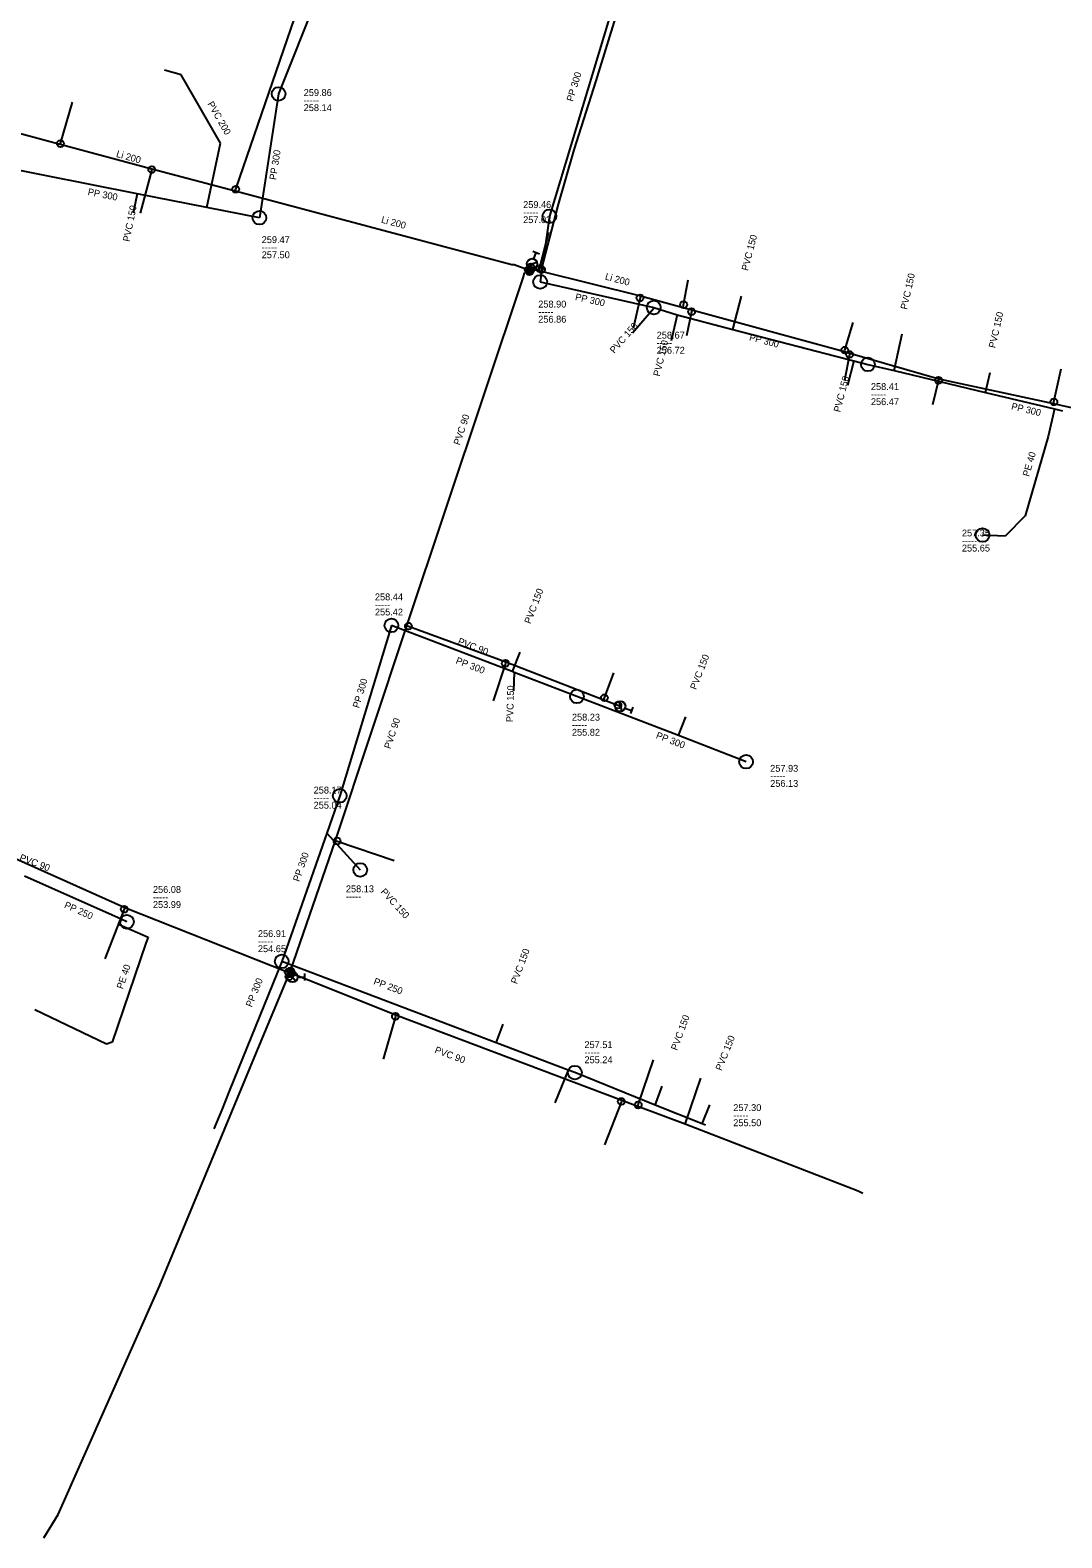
# Model space of a CAD drawing. Extents: x -771681 to -770485, y -1050143 to -1049574.
# Drawn here: x -770902.2 to -770751.8, y -1050118.2 to -1049898.6 of the extents above; entities that cross this region are included whole.
import ezdxf

# ---------------------------------------------------------------- set-up
doc = ezdxf.new("R2010")
doc.units = 0
doc.layers.add('Level 0', color=7, linetype='Continuous')

msp = doc.modelspace()

# ---------------------------------------------------------------- linework, layer by layer
at = {"layer": 'Level 0'}
for p, q in [((-770872.22, -1049921.74), (-770853.82, -1049868.4)), ((-770858.09, -1049887.99), (-770865.96, -1049907.86)), ((-770817.79, -1049896.87), (-770826.51, -1049925.68)), ((-770819.69, -1049905.97), (-770816.69, -1049896.18)), ((-770880.16, -1049905.07), (-770882.61, -1049904.41)), ((-770874.42, -1049915.05), (-770880.16, -1049905.07)), ((-770822.88, -1049916), (-770819.69, -1049905.97)), ((-770865.96, -1049907.86), (-770868.76, -1049925.9)), ((-770897.76, -1049915.1), (-770896.01, -1049909.08)), ((-770905.19, -1049913.2), (-770899.25, -1049914.79)), ((-770899.25, -1049914.79), (-770897.79, -1049915.2)), ((-770897.79, -1049915.2), (-770897.76, -1049915.1)), ((-770876.41, -1049924.39), (-770874.42, -1049915.05)), ((-770897.79, -1049915.2), (-770884.42, -1049918.76)), ((-770825.21, -1049924.11), (-770822.88, -1049916)), ((-770886.57, -1049922.39), (-770910.53, -1049917.67)), ((-770884.45, -1049918.87), (-770886.12, -1049925.24)), ((-770884.42, -1049918.76), (-770884.45, -1049918.87)), ((-770884.42, -1049918.76), (-770872.3, -1049921.99)), ((-770886.57, -1049922.39), (-770887.14, -1049925.24)), ((-770876.41, -1049924.39), (-770886.57, -1049922.39)), ((-770872.3, -1049921.99), (-770872.22, -1049921.74)), ((-770872.3, -1049921.99), (-770831.99, -1049932.72)), ((-770868.76, -1049925.9), (-770876.41, -1049924.39)), ((-770826.51, -1049925.68), (-770827.85, -1049935.25)), ((-770827.65, -1049933.44), (-770825.21, -1049924.11)), ((-770827.93, -1049933.3), (-770826.57, -1049927.98)), ((-770829.74, -1049932.83), (-770828.32, -1049932.37)), ((-770829.22, -1049933.05), (-770829.03, -1049932.6)), ((-770828.9, -1049930.78), (-770827.96, -1049931.13)), ((-770828.77, -1049931.9), (-770828.43, -1049930.96)), ((-770847.26, -1049985.32), (-770830.28, -1049934.52)), ((-770831.99, -1049932.72), (-770831.63, -1049932.73)), ((-770831.63, -1049932.73), (-770829.57, -1049933.49)), ((-770830.28, -1049934.52), (-770830.12, -1049933.89)), ((-770830.12, -1049933.89), (-770829.39, -1049933.89)), ((-770829.57, -1049933.49), (-770829.33, -1049933.52)), ((-770829.39, -1049933.76), (-770829.33, -1049933.52)), ((-770829.39, -1049933.89), (-770829.39, -1049933.76)), ((-770829.33, -1049933.52), (-770829.22, -1049933.05)), ((-770829.33, -1049933.52), (-770829.24, -1049933.52)), ((-770829.24, -1049933.52), (-770828.87, -1049933.43)), ((-770828.87, -1049933.43), (-770828.04, -1049933.62)), ((-770828.04, -1049933.62), (-770827.93, -1049933.3)), ((-770828.04, -1049933.62), (-770828.01, -1049933.63)), ((-770828.01, -1049933.63), (-770827.7, -1049933.66)), ((-770827.65, -1049933.44), (-770827.7, -1049933.66)), ((-770827.7, -1049933.66), (-770813.22, -1049937.25)), ((-770827.85, -1049935.25), (-770811.3, -1049938.97)), ((-770806.94, -1049938.57), (-770806.26, -1049934.93)), ((-770811.32, -1049939.17), (-770814.39, -1049942.69)), ((-770813.29, -1049937.57), (-770814.32, -1049942.01)), ((-770813.22, -1049937.25), (-770813.29, -1049937.57)), ((-770813.22, -1049937.25), (-770807.01, -1049938.95)), ((-770811.3, -1049938.97), (-770807.88, -1049940.06)), ((-770807.01, -1049938.95), (-770806.94, -1049938.57)), ((-770807.01, -1049938.95), (-770805.73, -1049939.3)), ((-770799.78, -1049942.16), (-770798.52, -1049937.34)), ((-770807.88, -1049940.06), (-770808.78, -1049943.83)), ((-770807.88, -1049940.06), (-770799.78, -1049942.16)), ((-770805.79, -1049939.59), (-770806.53, -1049943.12)), ((-770805.73, -1049939.3), (-770805.79, -1049939.59)), ((-770805.73, -1049939.3), (-770783.52, -1049945.37)), ((-770783.46, -1049945.18), (-770782.23, -1049941.14)), ((-770799.78, -1049942.16), (-770782.16, -1049946.72)), ((-770776.28, -1049948.17), (-770775.09, -1049942.83)), ((-770783.52, -1049945.37), (-770783.46, -1049945.18)), ((-770783.52, -1049945.37), (-770782.73, -1049945.6)), ((-770782.77, -1049945.81), (-770783.49, -1049949.6)), ((-770782.73, -1049945.6), (-770782.77, -1049945.81)), ((-770782.73, -1049945.6), (-770769.73, -1049949.34)), ((-770782.16, -1049946.72), (-770783.08, -1049950.34)), ((-770782.16, -1049946.72), (-770780.08, -1049947.26)), ((-770780.08, -1049947.26), (-770776.28, -1049948.17)), ((-770752.99, -1049952.72), (-770751.92, -1049947.92)), ((-770776.28, -1049948.17), (-770762.96, -1049951.35)), ((-770769.79, -1049949.58), (-770770.67, -1049953.14)), ((-770769.73, -1049949.34), (-770769.79, -1049949.58)), ((-770769.73, -1049949.34), (-770753.04, -1049952.96)), ((-770762.96, -1049951.35), (-770762.29, -1049948.45)), ((-770762.96, -1049951.35), (-770752.89, -1049953.75)), ((-770752.89, -1049953.75), (-770753.82, -1049957.74)), ((-770753.04, -1049952.96), (-770752.99, -1049952.72)), ((-770753.04, -1049952.96), (-770734.86, -1049957.12)), ((-770752.89, -1049953.75), (-770751.73, -1049954.03)), ((-770753.82, -1049957.74), (-770757.19, -1049969.34)), ((-770757.19, -1049969.34), (-770760.1, -1049972.28)), ((-770760.1, -1049972.28), (-770763.38, -1049972.12)), ((-770857.66, -1050016.63), (-770847.26, -1049985.32)), ((-770849.53, -1049985.29), (-770857.05, -1050010.1)), ((-770831.91, -1049992.02), (-770849.53, -1049985.29)), ((-770847.26, -1049985.32), (-770847.04, -1049985.39)), ((-770847.04, -1049985.39), (-770832.84, -1049990.57)), ((-770830.81, -1049989.18), (-770831.91, -1049992.02)), ((-770832.92, -1049990.81), (-770834.68, -1049996.29)), ((-770832.84, -1049990.57), (-770832.92, -1049990.81)), ((-770832.84, -1049990.57), (-770818.58, -1049996.1)), ((-770831.65, -1049992.12), (-770831.91, -1049992.02)), ((-770831.65, -1049992.12), (-770831.74, -1049994.81)), ((-770822.49, -1049995.62), (-770831.65, -1049992.12)), ((-770818.48, -1049995.83), (-770817.12, -1049992.21)), ((-770807.7, -1050001.34), (-770822.49, -1049995.62)), ((-770818.58, -1049996.1), (-770818.48, -1049995.83)), ((-770818.58, -1049996.1), (-770816.53, -1049996.9)), ((-770816.41, -1049996.35), (-770815.95, -1049997.77)), ((-770816.53, -1049996.9), (-770816.18, -1049997.06)), ((-770815.48, -1049997.32), (-770814.54, -1049997.66)), ((-770814.36, -1049997.19), (-770814.71, -1049998.13)), ((-770807.7, -1050001.34), (-770806.62, -1049998.58)), ((-770797.85, -1050005.15), (-770807.7, -1050001.34)), ((-770857.05, -1050010.1), (-770858.96, -1050015.54)), ((-770858.96, -1050015.54), (-770865.51, -1050034.22)), ((-770858.96, -1050015.54), (-770854.06, -1050020.91)), ((-770910.81, -1050016.36), (-770888.36, -1050026.38)), ((-770864.21, -1050035.62), (-770857.66, -1050016.63)), ((-770857.66, -1050016.63), (-770857.44, -1050016.7)), ((-770857.44, -1050016.7), (-770849.14, -1050019.54)), ((-770888.9, -1050028.09), (-770903.01, -1050021.79)), ((-770888.45, -1050026.62), (-770891.3, -1050033.86)), ((-770888.36, -1050026.38), (-770888.45, -1050026.62)), ((-770888.36, -1050026.38), (-770864.55, -1050035.79)), ((-770888.9, -1050028.09), (-770889.22, -1050028.85)), ((-770889.22, -1050028.85), (-770884.96, -1050030.68)), ((-770888.07, -1050028.46), (-770888.9, -1050028.09)), ((-770884.96, -1050030.68), (-770885.32, -1050031.55)), ((-770885.32, -1050031.55), (-770890.21, -1050045.98)), ((-770865.51, -1050034.22), (-770873.16, -1050053.11)), ((-770834.27, -1050046.08), (-770865.51, -1050034.22)), ((-770864.56, -1050036.45), (-770864.32, -1050035.89)), ((-770864.55, -1050035.79), (-770864.32, -1050035.89)), ((-770864.4, -1050035.92), (-770863.48, -1050037.1)), ((-770864.32, -1050035.89), (-770864.21, -1050035.62)), ((-770864.32, -1050035.89), (-770864.07, -1050035.96)), ((-770869.01, -1050047), (-770864.56, -1050036.45)), ((-770864.56, -1050036.45), (-770864.44, -1050036.48)), ((-770864.44, -1050036.48), (-770863.94, -1050036.51)), ((-770864.07, -1050035.96), (-770848.87, -1050041.99)), ((-770863.19, -1050036.51), (-770862.19, -1050036.51)), ((-770862.19, -1050036.01), (-770862.19, -1050037.01)), ((-770891.05, -1050046.27), (-770901.5, -1050041.29)), ((-770848.94, -1050042.24), (-770850.75, -1050048.49)), ((-770848.87, -1050041.99), (-770848.94, -1050042.24)), ((-770848.87, -1050041.99), (-770815.93, -1050054.42)), ((-770834.27, -1050046.08), (-770833.25, -1050043.38)), ((-770890.21, -1050045.98), (-770891.05, -1050046.27)), ((-770823.78, -1050050.06), (-770834.27, -1050046.08)), ((-770883.32, -1050081.54), (-770869.01, -1050047)), ((-770813.56, -1050055.14), (-770811.35, -1050048.55)), ((-770823.78, -1050050.06), (-770825.7, -1050054.83)), ((-770822.8, -1050050.43), (-770823.78, -1050050.06)), ((-770811.07, -1050055.15), (-770822.8, -1050050.43)), ((-770806.63, -1050057.66), (-770804.44, -1050051.25)), ((-770873.16, -1050053.11), (-770874.26, -1050055.83)), ((-770811.07, -1050055.15), (-770810.06, -1050052.41)), ((-770816.01, -1050054.63), (-770818.47, -1050060.97)), ((-770815.93, -1050054.42), (-770816.01, -1050054.63)), ((-770815.93, -1050054.42), (-770813.61, -1050055.3)), ((-770813.61, -1050055.3), (-770813.56, -1050055.14)), ((-770813.61, -1050055.3), (-770806.71, -1050057.9)), ((-770804.25, -1050057.89), (-770811.07, -1050055.15)), ((-770804.25, -1050057.89), (-770803.14, -1050055.12)), ((-770874.26, -1050055.83), (-770875.4, -1050058.64)), ((-770806.71, -1050057.9), (-770806.63, -1050057.66)), ((-770803.76, -1050058.09), (-770804.25, -1050057.89)), ((-770806.71, -1050057.9), (-770781.5, -1050067.65)), ((-770781.5, -1050067.65), (-770780.84, -1050068)), ((-770898.07, -1050114.8), (-770883.32, -1050081.54)), ((-770900.16, -1050118.2), (-770898.07, -1050114.8))]:
    msp.add_line(p, q, dxfattribs=at)
for centre, radius in [((-770865.96, -1049907.86), 1), ((-770897.76, -1049915.1), 0.5), ((-770884.45, -1049918.87), 0.5), ((-770872.22, -1049921.74), 0.5), ((-770868.76, -1049925.9), 1), ((-770826.51, -1049925.68), 1), ((-770829.03, -1049932.6), 0.75), ((-770829.22, -1049933.05), 0.5), ((-770829.57, -1049933.49), 0.5), ((-770829.39, -1049933.76), 0.5), ((-770829.24, -1049933.52), 0.5), ((-770827.85, -1049935.25), 1), ((-770827.93, -1049933.3), 0.5), ((-770827.65, -1049933.44), 0.5), ((-770813.29, -1049937.57), 0.5), ((-770811.3, -1049938.97), 1), ((-770806.94, -1049938.57), 0.5), ((-770805.79, -1049939.59), 0.5), ((-770783.46, -1049945.18), 0.5), ((-770782.77, -1049945.81), 0.5), ((-770780.08, -1049947.26), 1), ((-770769.79, -1049949.58), 0.5), ((-770752.99, -1049952.72), 0.5), ((-770763.38, -1049972.12), 1), ((-770849.53, -1049985.29), 1), ((-770847.04, -1049985.39), 0.5), ((-770832.92, -1049990.81), 0.5), ((-770822.49, -1049995.62), 1), ((-770818.48, -1049995.83), 0.5), ((-770816.53, -1049996.9), 0.5), ((-770816.18, -1049997.06), 0.75), ((-770797.85, -1050005.15), 1), ((-770857.05, -1050010.1), 1), ((-770857.44, -1050016.7), 0.5), ((-770854.06, -1050020.91), 1), ((-770888.45, -1050026.62), 0.5), ((-770888.07, -1050028.46), 1), ((-770865.51, -1050034.22), 1), ((-770864.55, -1050035.79), 0.5), ((-770864.21, -1050035.62), 0.5), ((-770863.94, -1050036.51), 0.75), ((-770864.07, -1050035.96), 0.5), ((-770864.44, -1050036.48), 0.5), ((-770848.94, -1050042.24), 0.5), ((-770822.8, -1050050.43), 1), ((-770816.01, -1050054.63), 0.5), ((-770813.56, -1050055.14), 0.5)]:
    msp.add_circle(centre, radius, dxfattribs=at)

# ---------------------------------------------------------------- texts
for s, rotation, p in [('PP 300', 73.16, (-770823.08, -1049909.04)), ('PVC 200', 299.905, (-770876.38, -1049909.3)), ('Li 200', 344.314, (-770889.71, -1049917.02)), ('PP 300', 81.177, (-770866.34, -1049920.43)), ('PP 300', 348.864, (-770893.84, -1049922.57)), ('PVC 150', 78.69, (-770887.69, -1049929.45)), ('Li 200', 345.089, (-770851.09, -1049926.6)), ('PVC 150', 75.35, (-770797.57, -1049933.69)), ('Li 200', 345, (-770818.47, -1049934.88)), ('PVC 150', 77.437, (-770774.39, -1049939.33)), ('PP 300', 347.332, (-770822.82, -1049937.87)), ('PVC 150', 48.906, (-770817.05, -1049945.74)), ('PVC 150', 76.991, (-770761.54, -1049944.95)), ('PP 300', 345.49, (-770797.45, -1049943.74)), ('PVC 150', 76.573, (-770810.42, -1049949.07)), ('PVC 150', 75.741, (-770784.13, -1049954.29)), ('PVC 90', 71.555, (-770839.57, -1049959.1)), ('PP 300', 346.595, (-770759.27, -1049953.8)), ('PE 40', 73.793, (-770756.61, -1049963.67)), ('PVC 150', 68.827, (-770829.27, -1049985.13)), ('PVC 90', 338.804, (-770839.94, -1049987.98)), ('PVC 150', 68.629, (-770805.12, -1049994.73)), ('PP 300', 338.962, (-770840.24, -1049990.79)), ('PP 300', 73.138, (-770854.25, -1049997.4)), ('PVC 150', 88.084, (-770831.81, -1049999.39)), ('PVC 90', 71.625, (-770849.68, -1050003.35)), ('PP 300', 338.853, (-770811.06, -1050001.68)), ('PP 300', 70.654, (-770862.97, -1050022.69)), ('PVC 90', 338.926, (-770903.82, -1050019.48)), ('PVC 150', 312.38, (-770851.16, -1050024.14)), ('PP 250', 335.94, (-770897.3, -1050026.37)), ('PVC 150', 69.305, (-770831.24, -1050037.6)), ('PE 40', 71.28, (-770888.67, -1050038.33)), ('PP 300', 67.981, (-770869.88, -1050040.97)), ('PP 250', 339.223, (-770852.22, -1050037.52)), ('PVC 150', 69.765, (-770807.9, -1050047.27)), ('PVC 90', 339.353, (-770843.31, -1050047.51)), ('PVC 150', 68.163, (-770801.42, -1050050.23))]:
    msp.add_text(s, height=1, rotation=rotation, dxfattribs=at).set_placement(p)
for s, p in [('259.86', (-770862.31, -1049908.16)), ('-----', (-770862.31, -1049909.26)), ('258.14', (-770862.31, -1049910.36)), ('259.46', (-770830.33, -1049924.48)), ('-----', (-770830.33, -1049925.58)), ('257.03', (-770830.33, -1049926.68)), ('-----', (-770868.43, -1049930.69)), ('259.47', (-770868.43, -1049929.59)), ('257.50', (-770868.43, -1049931.79)), ('258.90', (-770828.13, -1049938.98)), ('-----', (-770828.13, -1049940.08)), ('256.86', (-770828.13, -1049941.18)), ('258.67', (-770810.87, -1049943.5)), ('-----', (-770810.87, -1049944.6)), ('256.72', (-770810.87, -1049945.7)), ('258.41', (-770779.65, -1049950.99)), ('-----', (-770779.65, -1049952.09)), ('256.47', (-770779.65, -1049953.19)), ('257.35', (-770766.39, -1049972.32)), ('-----', (-770766.39, -1049973.42)), ('255.65', (-770766.39, -1049974.52)), ('258.44', (-770851.93, -1049981.63)), ('-----', (-770851.93, -1049982.73)), ('255.42', (-770851.93, -1049983.83)), ('258.23', (-770823.22, -1049999.15)), ('-----', (-770823.22, -1050000.25)), ('255.82', (-770823.22, -1050001.35)), ('-----', (-770794.33, -1050007.7)), ('257.93', (-770794.33, -1050006.6)), ('258.17', (-770860.86, -1050009.77)), ('256.13', (-770794.33, -1050008.8)), ('-----', (-770860.86, -1050010.87)), ('255.04', (-770860.86, -1050011.97)), ('-----', (-770884.28, -1050025.35)), ('256.08', (-770884.28, -1050024.25)), ('-----', (-770856.16, -1050025.26)), ('258.13', (-770856.16, -1050024.16)), ('253.99', (-770884.28, -1050026.45)), ('-----', (-770868.98, -1050031.78)), ('256.91', (-770868.98, -1050030.68)), ('254.65', (-770868.98, -1050032.88)), ('257.51', (-770821.4, -1050046.86)), ('-----', (-770821.4, -1050047.96)), ('255.24', (-770821.4, -1050049.06)), ('257.30', (-770799.71, -1050056.03)), ('-----', (-770799.71, -1050057.13)), ('255.50', (-770799.71, -1050058.23))]:
    msp.add_text(s, height=1, dxfattribs=at).set_placement(p)

doc.saveas('drawing.dxf')
